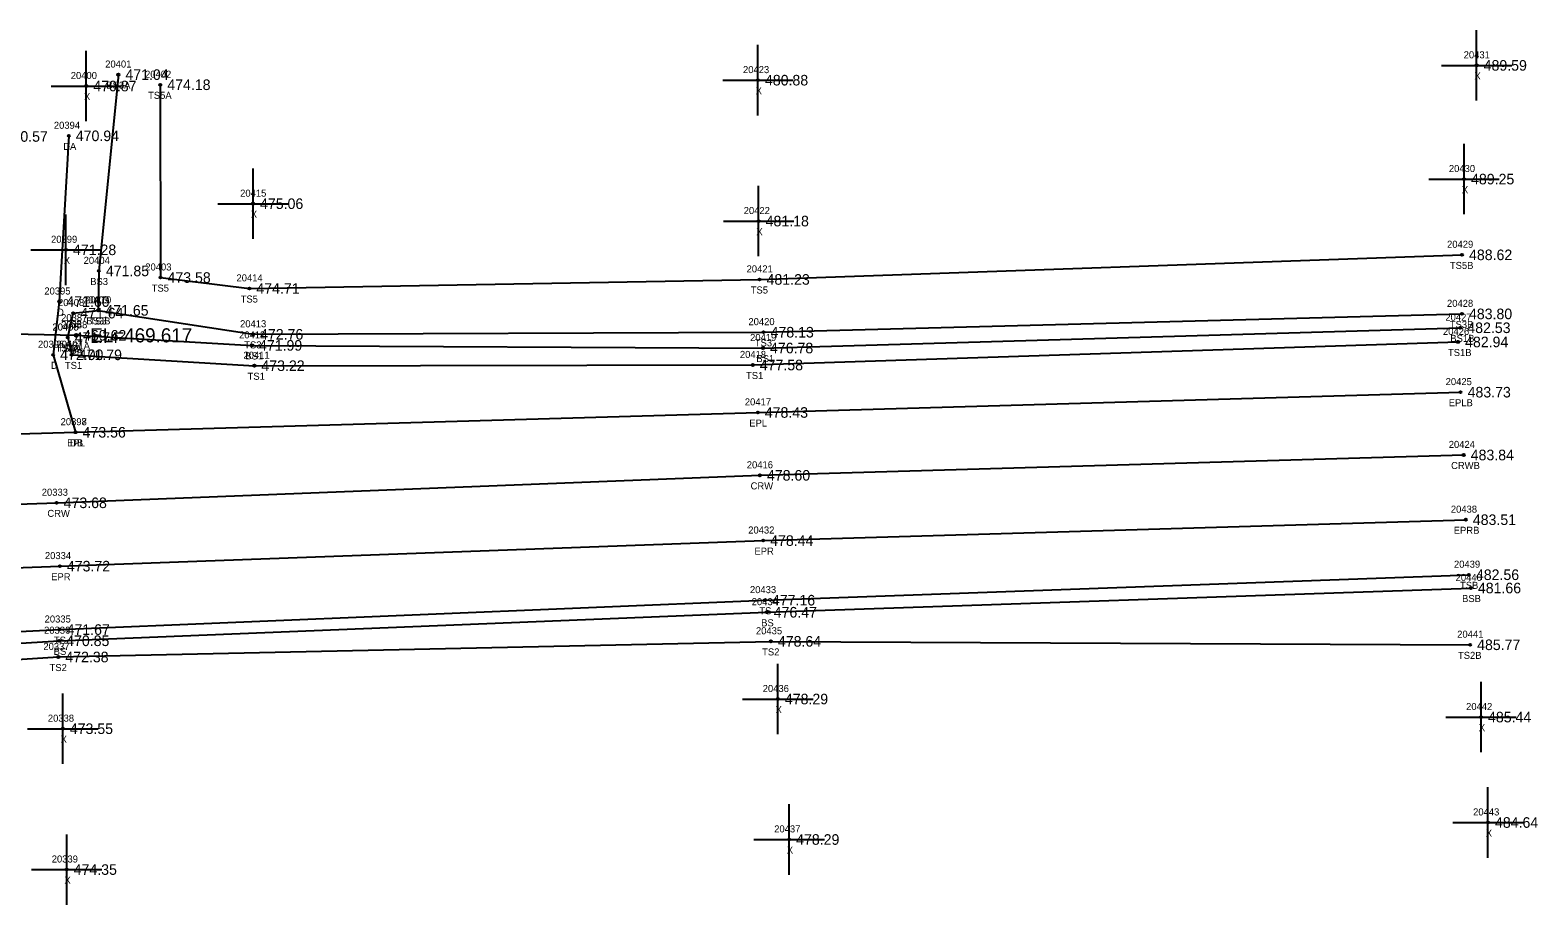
# Model space of a CAD drawing. Extents: x 1785066 to 1786589, y 770293 to 771312.
# Drawn here: x 1786374.9 to 1786589, y 770816.9 to 770941 of the extents above; entities that cross this region are included whole.
import ezdxf

# ---------------------------------------------------------------- set-up
doc = ezdxf.new("R2010")
doc.units = 0
for name, color, linetype in [('Default', 7, 'Continuous'), ('RD_DTM_BkLn1', 7, 'Continuous'), ('RD_DTM_BkLn2', 7, 'Continuous'), ('RD_DTM_BkLn_txCode', 7, 'Continuous'), ('RD_EX_DR_Pipe_txCode', 7, 'Continuous'), ('RD_EX_Driveway', 7, 'Continuous'), ('RD_EX_Driveway_txCode', 7, 'Continuous'), ('RD_EX_Misc', 7, 'Continuous'), ('RD_EX_Misc_txCode', 7, 'Continuous'), ('RD_EX_Road', 7, 'Continuous'), ('RD_EX_Road_txCode', 7, 'Continuous'), ('RD_EX_TX_Driveway_ELEV', 7, 'Continuous'), ('RD_EX_TX_Misc_ELEV', 7, 'Continuous'), ('RD_EX_TX_Road_ELEV', 7, 'Continuous'), ('RD_HC_Survey_ELEV', 7, 'Continuous'), ('RD_HC_Survey_txCode', 7, 'Continuous'), ('RD_SMD_Locator', 7, 'Continuous'), ('RD_TX_Pipe_ElevEX', 7, 'Continuous')]:
    doc.layers.add(name, color=color, linetype=linetype)

msp = doc.modelspace()

# ---------------------------------------------------------------- linework, layer by layer
at = {"layer": 'Default'}
msp.add_line((1786356.85, 770898.28), (1786381.45, 770897.7), dxfattribs=at)
at = {"layer": 'RD_DTM_BkLn1'}
msp.add_lwpolyline([(1785825, 770854.98), (1785879.1, 770857.22), (1785979.05, 770860.47), (1786078.95, 770863.87), (1786178.85, 770867.23), (1786278.74, 770870.52), (1786378.69, 770873.93), (1786478.55, 770877.83), (1786578.48, 770880.72)], dxfattribs=at)
at = {"layer": 'RD_DTM_BkLn2'}
for points in [[(1786387.46, 770934.7), (1786384.69, 770906.84), (1786384.61, 770901.24)], [(1786393.41, 770933.26), (1786393.44, 770905.9), (1786406.06, 770904.35), (1786478.5, 770905.63), (1786578.24, 770909.12)], [(1786380.27, 770897.38), (1786381.05, 770900.85), (1786384.61, 770901.24), (1786406.58, 770897.84), (1786479.07, 770898.14), (1786578.23, 770900.74)], [(1786380.27, 770897.38), (1786380.83, 770894.93), (1786406.77, 770893.39), (1786477.54, 770893.49), (1786577.68, 770896.76)], [(1786381.45, 770897.7), (1786406.43, 770896.27), (1786478.99, 770895.9), (1786578, 770898.77)], [(1786246.96, 770847.38), (1786248.77, 770851.12), (1786279.67, 770850.97), (1786379.11, 770855.94), (1786479.26, 770860.11), (1786579.22, 770863.72)], [(1786249.47, 770848.15), (1786280.2, 770848.37), (1786379.05, 770854.35), (1786479.51, 770858.4), (1786579.5, 770861.84)], [(1786246.96, 770847.38), (1786249.88, 770844.07), (1786279.41, 770845.63), (1786378.93, 770852.05), (1786480.11, 770854.27), (1786579.39, 770853.78)]]:
    msp.add_lwpolyline(points, dxfattribs=at)
at = {"layer": 'RD_EX_Driveway'}
msp.add_lwpolyline([(1786380.42, 770926.01), (1786379.07, 770902.49), (1786378.19, 770894.94), (1786381.38, 770883.94)], dxfattribs=at)
at = {"layer": 'RD_EX_Misc'}
for p, q in [((1786580.32, 770931.01), (1786580.32, 770941.01)), ((1786382.9, 770928.08), (1786382.9, 770938.08)), ((1786478.27, 770928.91), (1786478.27, 770938.91)), ((1786575.32, 770936.01), (1786585.32, 770936.01)), ((1786473.27, 770933.91), (1786483.27, 770933.91)), ((1786377.9, 770933.08), (1786387.9, 770933.08)), ((1786578.53, 770914.87), (1786578.53, 770924.87)), ((1786406.58, 770911.38), (1786406.58, 770921.38)), ((1786478.37, 770908.91), (1786478.37, 770918.91)), ((1786573.53, 770919.87), (1786583.53, 770919.87)), ((1786380.02, 770904.83), (1786380.02, 770914.83)), ((1786401.58, 770916.38), (1786411.58, 770916.38)), ((1786473.37, 770913.91), (1786483.37, 770913.91)), ((1786375.02, 770909.83), (1786385.02, 770909.83)), ((1786481.1, 770841.08), (1786481.1, 770851.08)), ((1786580.94, 770838.52), (1786580.94, 770848.52)), ((1786379.57, 770836.87), (1786379.57, 770846.87)), ((1786476.1, 770846.08), (1786486.1, 770846.08)), ((1786374.57, 770841.87), (1786384.57, 770841.87)), ((1786575.94, 770843.52), (1786585.94, 770843.52)), ((1786581.93, 770823.56), (1786581.93, 770833.56)), ((1786482.7, 770821.15), (1786482.7, 770831.15)), ((1786380.12, 770816.88), (1786380.12, 770826.88)), ((1786576.93, 770828.56), (1786586.93, 770828.56)), ((1786477.7, 770826.15), (1786487.7, 770826.15)), ((1786375.12, 770821.88), (1786385.12, 770821.88))]:
    msp.add_line(p, q, dxfattribs=at)
at = {"layer": 'RD_EX_Road'}
for points in [[(1785824.57, 770864.86), (1785879.1, 770866.73), (1785977.08, 770869.67), (1786078.78, 770873.52), (1786179.09, 770876.83), (1786278.08, 770880.28), (1786358.72, 770883.31), (1786381.38, 770883.94), (1786478.25, 770886.75), (1786578.04, 770889.63)], [(1785825.31, 770845.6), (1785879.29, 770848.18), (1785979.17, 770851.29), (1786079.29, 770854.66), (1786178.79, 770858.1), (1786233.56, 770860.16), (1786246.2, 770860.52), (1786278.61, 770861.3), (1786379.15, 770864.94), (1786479.01, 770868.57), (1786578.78, 770871.53)]]:
    msp.add_lwpolyline(points, dxfattribs=at)
at = {"layer": 'RD_SMD_Locator'}
for centre, radius in [((1786580.32, 770936.01), 0.15), ((1786387.46, 770934.7), 0.15), ((1786478.27, 770933.91), 0.15), ((1786382.9, 770933.08), 0.15), ((1786393.41, 770933.26), 0.15), ((1786380.42, 770926.01), 0.15), ((1786578.53, 770919.87), 0.15), ((1786406.58, 770916.38), 0.15), ((1786478.37, 770913.91), 0.15), ((1786380.02, 770909.83), 0.15), ((1786578.24, 770909.12), 0.15), ((1786384.69, 770906.84), 0.15), ((1786393.44, 770905.9), 0.15), ((1786406.06, 770904.35), 0.15), ((1786478.5, 770905.63), 0.15), ((1786379.07, 770902.49), 0.15), ((1786381.05, 770900.85), 0.15), ((1786384.61, 770901.24), 0.15), ((1786384.61, 770901.24), 0.15), ((1786578.23, 770900.74), 0.15), ((1786380.27, 770897.38), 0.15), ((1786380.27, 770897.38), 0.15), ((1786381.45, 770897.7), 0.2), ((1786381.45, 770897.7), 0.15), ((1786406.58, 770897.84), 0.15), ((1786479.07, 770898.14), 0.15), ((1786578, 770898.77), 0.15), ((1786406.43, 770896.27), 0.15), ((1786478.99, 770895.9), 0.15), ((1786577.68, 770896.76), 0.15), ((1786378.19, 770894.94), 0.15), ((1786380.83, 770894.93), 0.15), ((1786406.77, 770893.39), 0.15), ((1786477.54, 770893.49), 0.15), ((1786578.04, 770889.63), 0.15), ((1786478.25, 770886.75), 0.15), ((1786381.38, 770883.94), 0.15), ((1786381.38, 770883.94), 0.15), ((1786578.48, 770880.72), 0.15), ((1786478.55, 770877.83), 0.15), ((1786378.69, 770873.93), 0.15), ((1786578.78, 770871.53), 0.15), ((1786479.01, 770868.57), 0.15), ((1786379.15, 770864.94), 0.15), ((1786579.22, 770863.72), 0.15), ((1786579.5, 770861.84), 0.15), ((1786479.26, 770860.11), 0.15), ((1786479.51, 770858.4), 0.15), ((1786379.05, 770854.35), 0.15), ((1786379.11, 770855.94), 0.15), ((1786480.11, 770854.27), 0.15), ((1786579.39, 770853.78), 0.15), ((1786378.93, 770852.05), 0.15), ((1786481.1, 770846.08), 0.15), ((1786379.57, 770841.87), 0.15), ((1786580.94, 770843.52), 0.15), ((1786581.93, 770828.56), 0.15), ((1786482.7, 770826.15), 0.15), ((1786380.12, 770821.88), 0.15)]:
    msp.add_circle(centre, radius, dxfattribs=at)

# ---------------------------------------------------------------- texts
at = {"layer": 'RD_DTM_BkLn_txCode'}
for s, p in [('20401', (1786385.59, 770935.7)), ('BS3A', (1786385.75, 770932.7)), ('20402', (1786391.25, 770934.26)), ('TS5A', (1786391.68, 770931.26)), ('20429', (1786576.12, 770910.12)), ('20404', (1786382.53, 770907.84)), ('TS5B', (1786576.52, 770907.12)), ('BS3', (1786383.46, 770904.84)), ('20403', (1786391.28, 770906.9)), ('20414', (1786404.23, 770905.35)), ('20421', (1786476.66, 770906.63)), ('TS5', (1786392.19, 770903.9)), ('TS5', (1786477.25, 770903.63)), ('20408', (1786378.89, 770901.85)), ('20409', (1786382.45, 770902.24)), ('20410', (1786382.73, 770902.24)), ('TS5', (1786404.82, 770902.35)), ('20428', (1786576.11, 770901.74)), ('20388', (1786379.33, 770898.7)), ('TS3', (1786379.8, 770898.85)), ('BS3B', (1786382.91, 770899.24)), ('TS3', (1786383.36, 770899.24)), ('20413', (1786404.74, 770898.84)), ('20420', (1786476.92, 770899.14)), ('20427', (1786575.88, 770899.77)), ('TS3B', (1786576.51, 770898.74)), ('20406', (1786378.09, 770898.38)), ('20405', (1786378.11, 770898.38)), ('20412', (1786404.6, 770897.27)), ('20419', (1786477.16, 770896.9)), ('20426', (1786575.54, 770897.76)), ('BS1B', (1786576.58, 770896.77)), ('TS3A', (1786378.54, 770895.38)), ('20407', (1786378.67, 770895.93)), ('TS1A', (1786378.82, 770895.38)), ('BS1A', (1786380.01, 770895.7)), ('20411', (1786405.22, 770894.39)), ('TS3', (1786405.33, 770895.84)), ('BS1', (1786405.48, 770894.27)), ('20418', (1786475.71, 770894.49)), ('TS3', (1786477.83, 770896.14)), ('TS1B', (1786576.25, 770894.76)), ('TS1', (1786379.87, 770892.93)), ('BS1', (1786478.05, 770893.9)), ('TS1', (1786405.81, 770891.39)), ('TS1', (1786476.58, 770891.49)), ('20439', (1786577.1, 770864.72)), ('20440', (1786577.34, 770862.84)), ('20433', (1786477.14, 770861.11)), ('TSB', (1786577.96, 770861.72)), ('20434', (1786477.39, 770859.4)), ('TS', (1786478.47, 770858.11)), ('BSB', (1786578.25, 770859.84)), ('20335', (1786376.99, 770856.94)), ('BS', (1786478.73, 770856.4)), ('20336', (1786376.91, 770855.35)), ('TS', (1786378.31, 770853.94)), ('20435', (1786477.99, 770855.27)), ('20441', (1786577.56, 770854.78)), ('20337', (1786376.81, 770853.05)), ('BS', (1786378.28, 770852.35)), ('TS2', (1786478.87, 770852.27)), ('TS2B', (1786577.67, 770851.78)), ('TS2', (1786377.69, 770850.05))]:
    msp.add_text(s, height=1, dxfattribs=at).set_placement(p)
at = {"layer": 'RD_EX_DR_Pipe_txCode'}
for s, p in [('20387', (1786379.33, 770899.7)), ('PB', (1786380.67, 770894.7))]:
    msp.add_text(s, height=1, dxfattribs=at).set_placement(p)
at = {"layer": 'RD_EX_Driveway_txCode'}
for s, p in [('20394', (1786378.3, 770927.01)), ('DA', (1786379.63, 770924.01)), ('20395', (1786376.95, 770903.49)), ('D', (1786378.76, 770900.49)), ('20396', (1786376.05, 770895.94)), ('D', (1786377.89, 770892.94)), ('20397', (1786379.26, 770884.94)), ('DB', (1786380.6, 770881.94))]:
    msp.add_text(s, height=1, dxfattribs=at).set_placement(p)
at = {"layer": 'RD_EX_Misc_txCode'}
for s, p in [('20431', (1786578.48, 770937.01)), ('20423', (1786476.15, 770934.91)), ('20400', (1786380.7, 770934.08)), ('X', (1786580, 770934.01)), ('X', (1786382.58, 770931.08)), ('X', (1786477.95, 770931.91)), ('20430', (1786576.38, 770920.87)), ('X', (1786578.22, 770917.87)), ('20415', (1786404.75, 770917.38)), ('X', (1786406.27, 770914.38)), ('20422', (1786476.25, 770914.91)), ('X', (1786478.05, 770911.91)), ('20399', (1786377.9, 770910.83)), ('X', (1786379.71, 770907.83)), ('20436', (1786478.95, 770847.08)), ('20338', (1786377.45, 770842.87)), ('X', (1786480.78, 770844.08)), ('20442', (1786578.82, 770844.52)), ('X', (1786580.63, 770841.52)), ('X', (1786379.26, 770839.87)), ('20443', (1786579.82, 770829.56)), ('20437', (1786480.58, 770827.15)), ('X', (1786581.62, 770826.56)), ('X', (1786482.38, 770824.15)), ('20339', (1786378, 770822.88)), ('X', (1786379.8, 770819.88))]:
    msp.add_text(s, height=1, dxfattribs=at).set_placement(p)
at = {"layer": 'RD_EX_Road_txCode'}
for s, p in [('20425', (1786575.92, 770890.63)), ('20417', (1786476.41, 770887.75)), ('EPLB', (1786576.36, 770887.63)), ('20398', (1786379.26, 770884.94)), ('EPL', (1786477.04, 770884.75)), ('EPL', (1786380.18, 770881.94)), ('20438', (1786576.66, 770872.53)), ('20432', (1786476.89, 770869.57)), ('EPRB', (1786577.07, 770869.53)), ('EPR', (1786477.78, 770866.57)), ('20334', (1786377.03, 770865.94)), ('EPR', (1786377.92, 770862.94))]:
    msp.add_text(s, height=1, dxfattribs=at).set_placement(p)
at = {"layer": 'RD_EX_TX_Driveway_ELEV'}
for s, p in [('470.57', (1786371.31, 770925.17)), ('470.94', (1786381.42, 770925.26)), ('471.60', (1786380.07, 770901.74)), ('472.00', (1786379.19, 770894.19)), ('473.56', (1786382.38, 770883.19))]:
    msp.add_text(s, height=1.5, dxfattribs=at).set_placement(p)
at = {"layer": 'RD_EX_TX_Misc_ELEV'}
for s, p in [('489.59', (1786581.32, 770935.26)), ('470.87', (1786383.9, 770932.33)), ('471.04', (1786388.46, 770933.95)), ('474.18', (1786394.41, 770932.51)), ('480.88', (1786479.27, 770933.16)), ('489.25', (1786579.53, 770919.12)), ('475.06', (1786407.58, 770915.63)), ('481.18', (1786479.37, 770913.16)), ('471.28', (1786381.02, 770909.08)), ('488.62', (1786579.24, 770908.37)), ('471.85', (1786385.69, 770906.09)), ('473.58', (1786394.44, 770905.15)), ('481.23', (1786479.5, 770904.88)), ('474.71', (1786407.06, 770903.6)), ('471.64', (1786382.05, 770900.1)), ('471.65', (1786385.61, 770900.49)), ('471.65', (1786385.61, 770900.49)), ('482.53', (1786579, 770898.02)), ('483.80', (1786579.23, 770899.99)), ('471.74', (1786381.27, 770896.63)), ('471.74', (1786381.27, 770896.63)), ('469.62', (1786382.45, 770896.95)), ('472.76', (1786407.58, 770897.09)), ('478.13', (1786480.07, 770897.39)), ('482.94', (1786578.68, 770896.01)), ('471.79', (1786381.83, 770894.18)), ('471.99', (1786407.43, 770895.52)), ('476.78', (1786479.99, 770895.15)), ('473.22', (1786407.77, 770892.64)), ('477.58', (1786478.54, 770892.74)), ('482.56', (1786580.22, 770862.97)), ('477.16', (1786480.26, 770859.36)), ('481.66', (1786580.5, 770861.09)), ('476.47', (1786480.51, 770857.65)), ('471.67', (1786380.11, 770855.19)), ('470.85', (1786380.05, 770853.6)), ('478.64', (1786481.11, 770853.52)), ('485.77', (1786580.39, 770853.03)), ('472.38', (1786379.93, 770851.3)), ('478.29', (1786482.1, 770845.33)), ('485.44', (1786581.94, 770842.77)), ('473.55', (1786380.57, 770841.12)), ('484.64', (1786582.93, 770827.81)), ('478.29', (1786483.7, 770825.4)), ('474.35', (1786381.12, 770821.13))]:
    msp.add_text(s, height=1.5, dxfattribs=at).set_placement(p)
at = {"layer": 'RD_EX_TX_Road_ELEV'}
for s, p in [('483.73', (1786579.04, 770888.88)), ('478.43', (1786479.25, 770886)), ('473.56', (1786382.38, 770883.19)), ('483.51', (1786579.78, 770870.78)), ('478.44', (1786480.01, 770867.82)), ('473.72', (1786380.15, 770864.19))]:
    msp.add_text(s, height=1.5, dxfattribs=at).set_placement(p)
at = {"layer": 'RD_HC_Survey_ELEV'}
for s, p in [('483.84', (1786579.48, 770879.97)), ('478.60', (1786479.55, 770877.08)), ('473.68', (1786379.69, 770873.18))]:
    msp.add_text(s, height=1.5, dxfattribs=at).set_placement(p)
at = {"layer": 'RD_HC_Survey_txCode'}
for s, p in [('20424', (1786576.36, 770881.72)), ('20416', (1786476.69, 770878.83)), ('CRWB', (1786576.69, 770878.72)), ('20333', (1786376.58, 770874.93)), ('CRW', (1786477.23, 770875.83)), ('CRW', (1786377.38, 770871.93))]:
    msp.add_text(s, height=1, dxfattribs=at).set_placement(p)
at = {"layer": 'RD_TX_Pipe_ElevEX'}
msp.add_text('EL=469.617', height=2, dxfattribs=at).set_placement((1786383.45, 770896.7))

doc.saveas('drawing.dxf')
